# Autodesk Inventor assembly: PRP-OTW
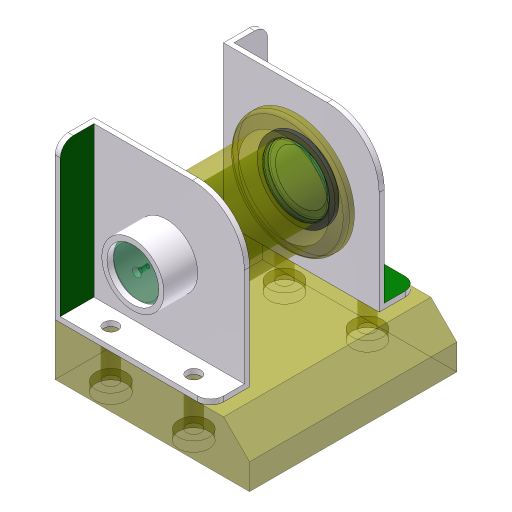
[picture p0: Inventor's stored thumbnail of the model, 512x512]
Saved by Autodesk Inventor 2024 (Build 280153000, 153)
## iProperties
Company: ATC
Created: 2023-03
Part Number: PRP-OTW
Document SubType Name: Assembly
Designer: Andrzej Jaskulski
Mass: 1986.93 g
Surface Area: 612.19 cm^2
Volume: 198.693 cm^3
Density: 10 g/cm^3
Stock Number: PRP
Checked By: A.J.
Engr Approved By: Andrzej Jaskulski
Mfg Approved By: Andrzej Jaskulski
Authority: A.J.
Title: A.J.: Kurs R2024-MEP
Author: Andrzej Jaskulski
Revision Number: 1/24
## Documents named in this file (4)
- C:\Users\AndJas\Documents\R2024-MEP\Obszar roboczy\PRP-OTW.iam
- C:\Users\AndJas\Documents\R2024-MEP\Obszar roboczy\PRP-Podstawa.ipt
- C:\Users\AndJas\Documents\R2024-MEP\Obszar roboczy\PRP-Podpora.ipt
- C:\Users\AndJas\Documents\R2024-MEP\Obszar roboczy\PRP-Zespół rolki.iam
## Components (4 placed, 3 different names)
1. PRP-Podstawa:1 — Zestawiający:1, Zestawiający:2, Zestawiający:3, Zestawiający:4
2. PRP-Podpora:1 — Zestawiający:1, Zestawiający:3, Wstaw:1
3. PRP-Podpora:2 — Zestawiający:2, Zestawiający:4
4. PRP-Zespół rolki:1 [sub-assembly] — Wstaw:1
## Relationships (5: Mate 4, Insert 1)
- Zestawiający:1 [Mate]: PRP-Podstawa:1 ↔ PRP-Podpora:1
- Zestawiający:2 [Mate]: PRP-Podstawa:1 ↔ PRP-Podpora:2
- Zestawiający:3 [Mate]: PRP-Podstawa:1 ↔ PRP-Podpora:1
- Zestawiający:4 [Mate]: PRP-Podstawa:1 ↔ PRP-Podpora:2
- Wstaw:1 [Insert]: PRP-Podpora:1 ↔ PRP-Zespół rolki:1
